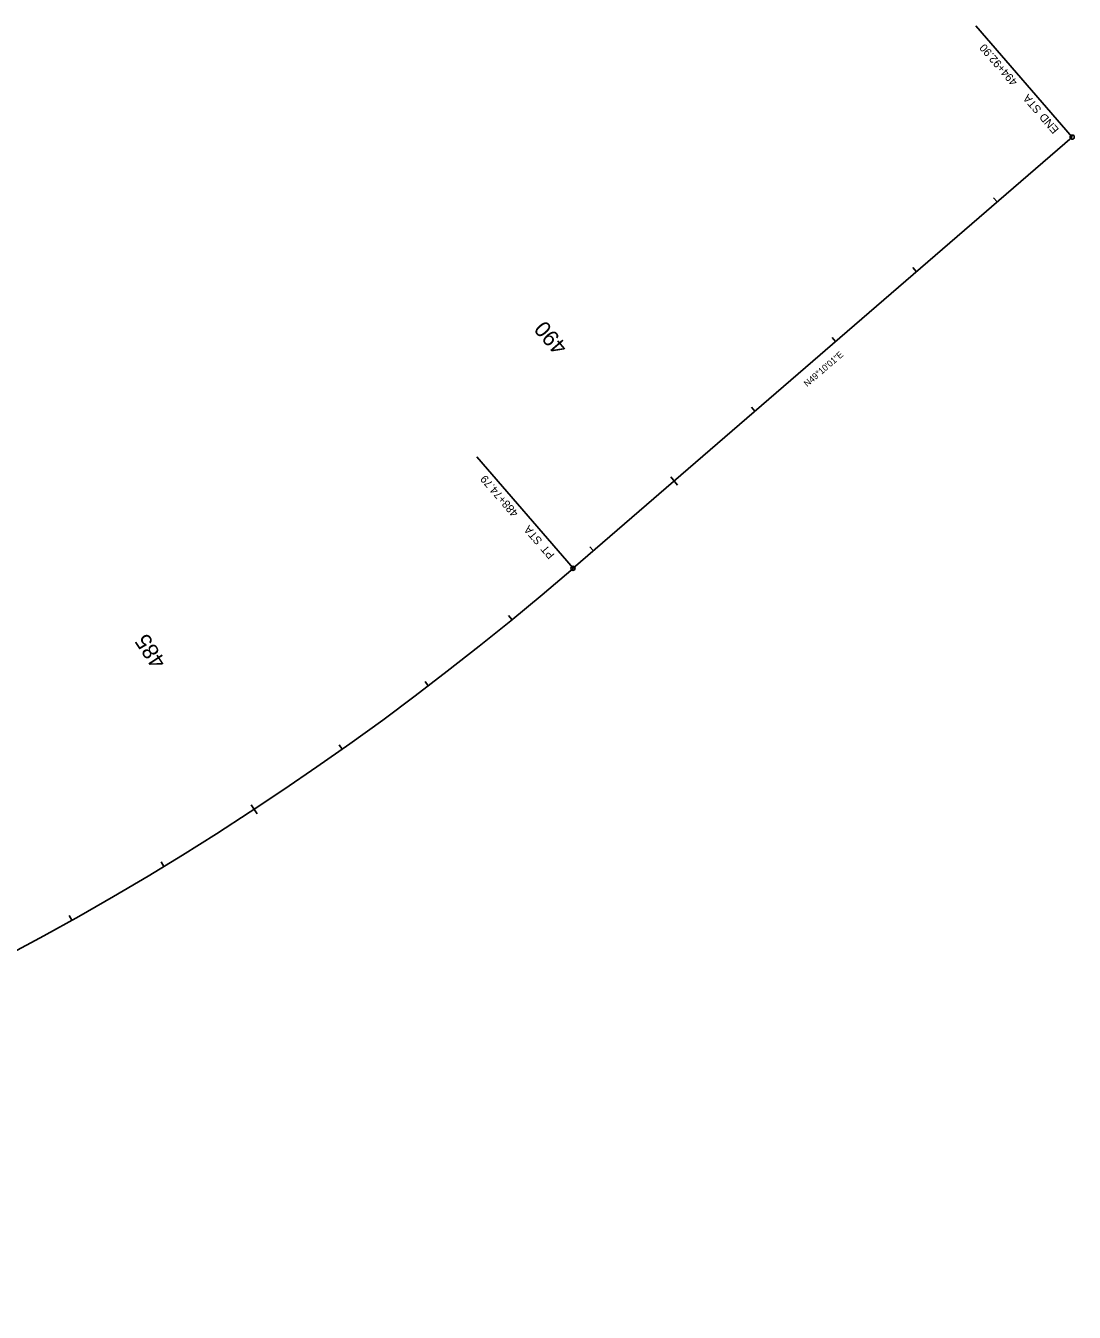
# Model space of a CAD drawing. Extents: x 1698762 to 1703402, y 997897 to 1000251.
# Drawn here: x 1702420 to 1703402, y 999045 to 1000251 of the extents above; entities that cross this region are included whole.
import ezdxf

# ---------------------------------------------------------------- set-up
doc = ezdxf.new("R2010")
doc.units = 0
for name, color, linetype in [('Default', 7, 'Continuous'), ('Modeling-Boundary-Existing', 7, 'Continuous'), ('Modeling-Contours-Minor-Existing', 7, 'Continuous'), ('Modeling-Hole-Existing', 7, 'Continuous'), ('Modeling-Island-Existing', 7, 'Continuous'), ('Modeling-Void-Existing', 7, 'Continuous'), ('Roadway-Proposed Bearing Label', 7, 'Continuous'), ('Roadway-Proposed Station Cardinal Points', 7, 'Continuous')]:
    doc.layers.add(name, color=color, linetype=linetype)

msp = doc.modelspace()

# ---------------------------------------------------------------- linework, layer by layer
at = {"layer": 'Default'}
msp.add_arc((1701059.2, 1001909.7), 2864.8, 262.6986, 310.8329, dxfattribs=at)
at = {"layer": 'Modeling-Boundary-Existing'}
for p, q in [((1703329.8, 1000085.6), (1703326.5, 1000089.4)), ((1703254.1, 1000020.2), (1703250.8, 1000024)), ((1703178.4, 999954.8), (1703175.2, 999958.6)), ((1703102.8, 999889.4), (1703099.5, 999893.2)), ((1702951.5, 999758.6), (1702948.2, 999762.4)), ((1702875.2, 999694), (1702872, 999697.9)), ((1702796.7, 999632), (1702793.7, 999636)), ((1702716.2, 999572.7), (1702713.3, 999576.8)), ((1702549.1, 999462.8), (1702546.5, 999467.1)), ((1702462.8, 999412.3), (1702460.4, 999416.7))]:
    msp.add_line(p, q, dxfattribs=at)
at = {"layer": 'Modeling-Contours-Minor-Existing'}
msp.add_line((1702932.4, 999742.2), (1703400.1, 1000146.3), dxfattribs=at)
msp.add_arc((1701059.2, 1001909.7), 2864.8, 262.6986, 310.8329, dxfattribs=at)
at = {"layer": 'Modeling-Hole-Existing'}
for p, q in [((1703023.9, 999827.8), (1703030.4, 999820.2)), ((1702630.9, 999520.5), (1702636.4, 999512.1))]:
    msp.add_line(p, q, dxfattribs=at)
at = {"layer": 'Modeling-Void-Existing'}
for p, q in [((1703400.1, 1000146.3), (1703309.8, 1000250.7)), ((1703309.8, 1000250.7), (1703309.8, 1000250.7)), ((1702932.4, 999742.2), (1702842.1, 999846.6)), ((1702842.1, 999846.6), (1702842.1, 999846.6))]:
    msp.add_line(p, q, dxfattribs=at)
for centre in [(1703400.1, 1000146.3), (1702932.4, 999742.2)]:
    msp.add_circle(centre, 1.98, dxfattribs=at)

# ---------------------------------------------------------------- texts
at = {"layer": 'Modeling-Island-Existing'}
for s, rotation, p in [('490', 130.8331, (1702928, 999950.1)), ('485', 123.3371, (1702551.8, 999654.3))]:
    msp.add_text(s, height=15, rotation=rotation, dxfattribs=at).set_placement(p)
at = {"layer": 'Roadway-Proposed Bearing Label'}
msp.add_text('N49°10\'01"E', height=6, rotation=40.8331, dxfattribs=at).set_placement((1703151.8, 999911.9))
at = {"layer": 'Roadway-Proposed Station Cardinal Points'}
for s, p in [('494+92.90', (1703349.4, 1000198.4)), (' STA ', (1703373.6, 1000170.4)), ('END', (1703388.1, 1000153.6)), ('488+74.79', (1702881.7, 999794.2)), (' STA ', (1702905.9, 999766.2)), ('PT', (1702915.6, 999755))]:
    msp.add_text(s, height=7.5, rotation=130.8331, dxfattribs=at).set_placement(p)

doc.saveas('drawing.dxf')
